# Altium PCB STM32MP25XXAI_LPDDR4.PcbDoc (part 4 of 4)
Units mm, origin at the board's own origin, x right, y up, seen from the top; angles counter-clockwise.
Board outline 172 x 137 mm, 4 copper layers (Top Layer, Signal Layer 1, Signal Layer 2, Bottom Layer), stack 1.614 mm thick; 188 components, 144 nets, 1216 pads, 838 vias.
Unrouted connection lines stored in the file: 13.
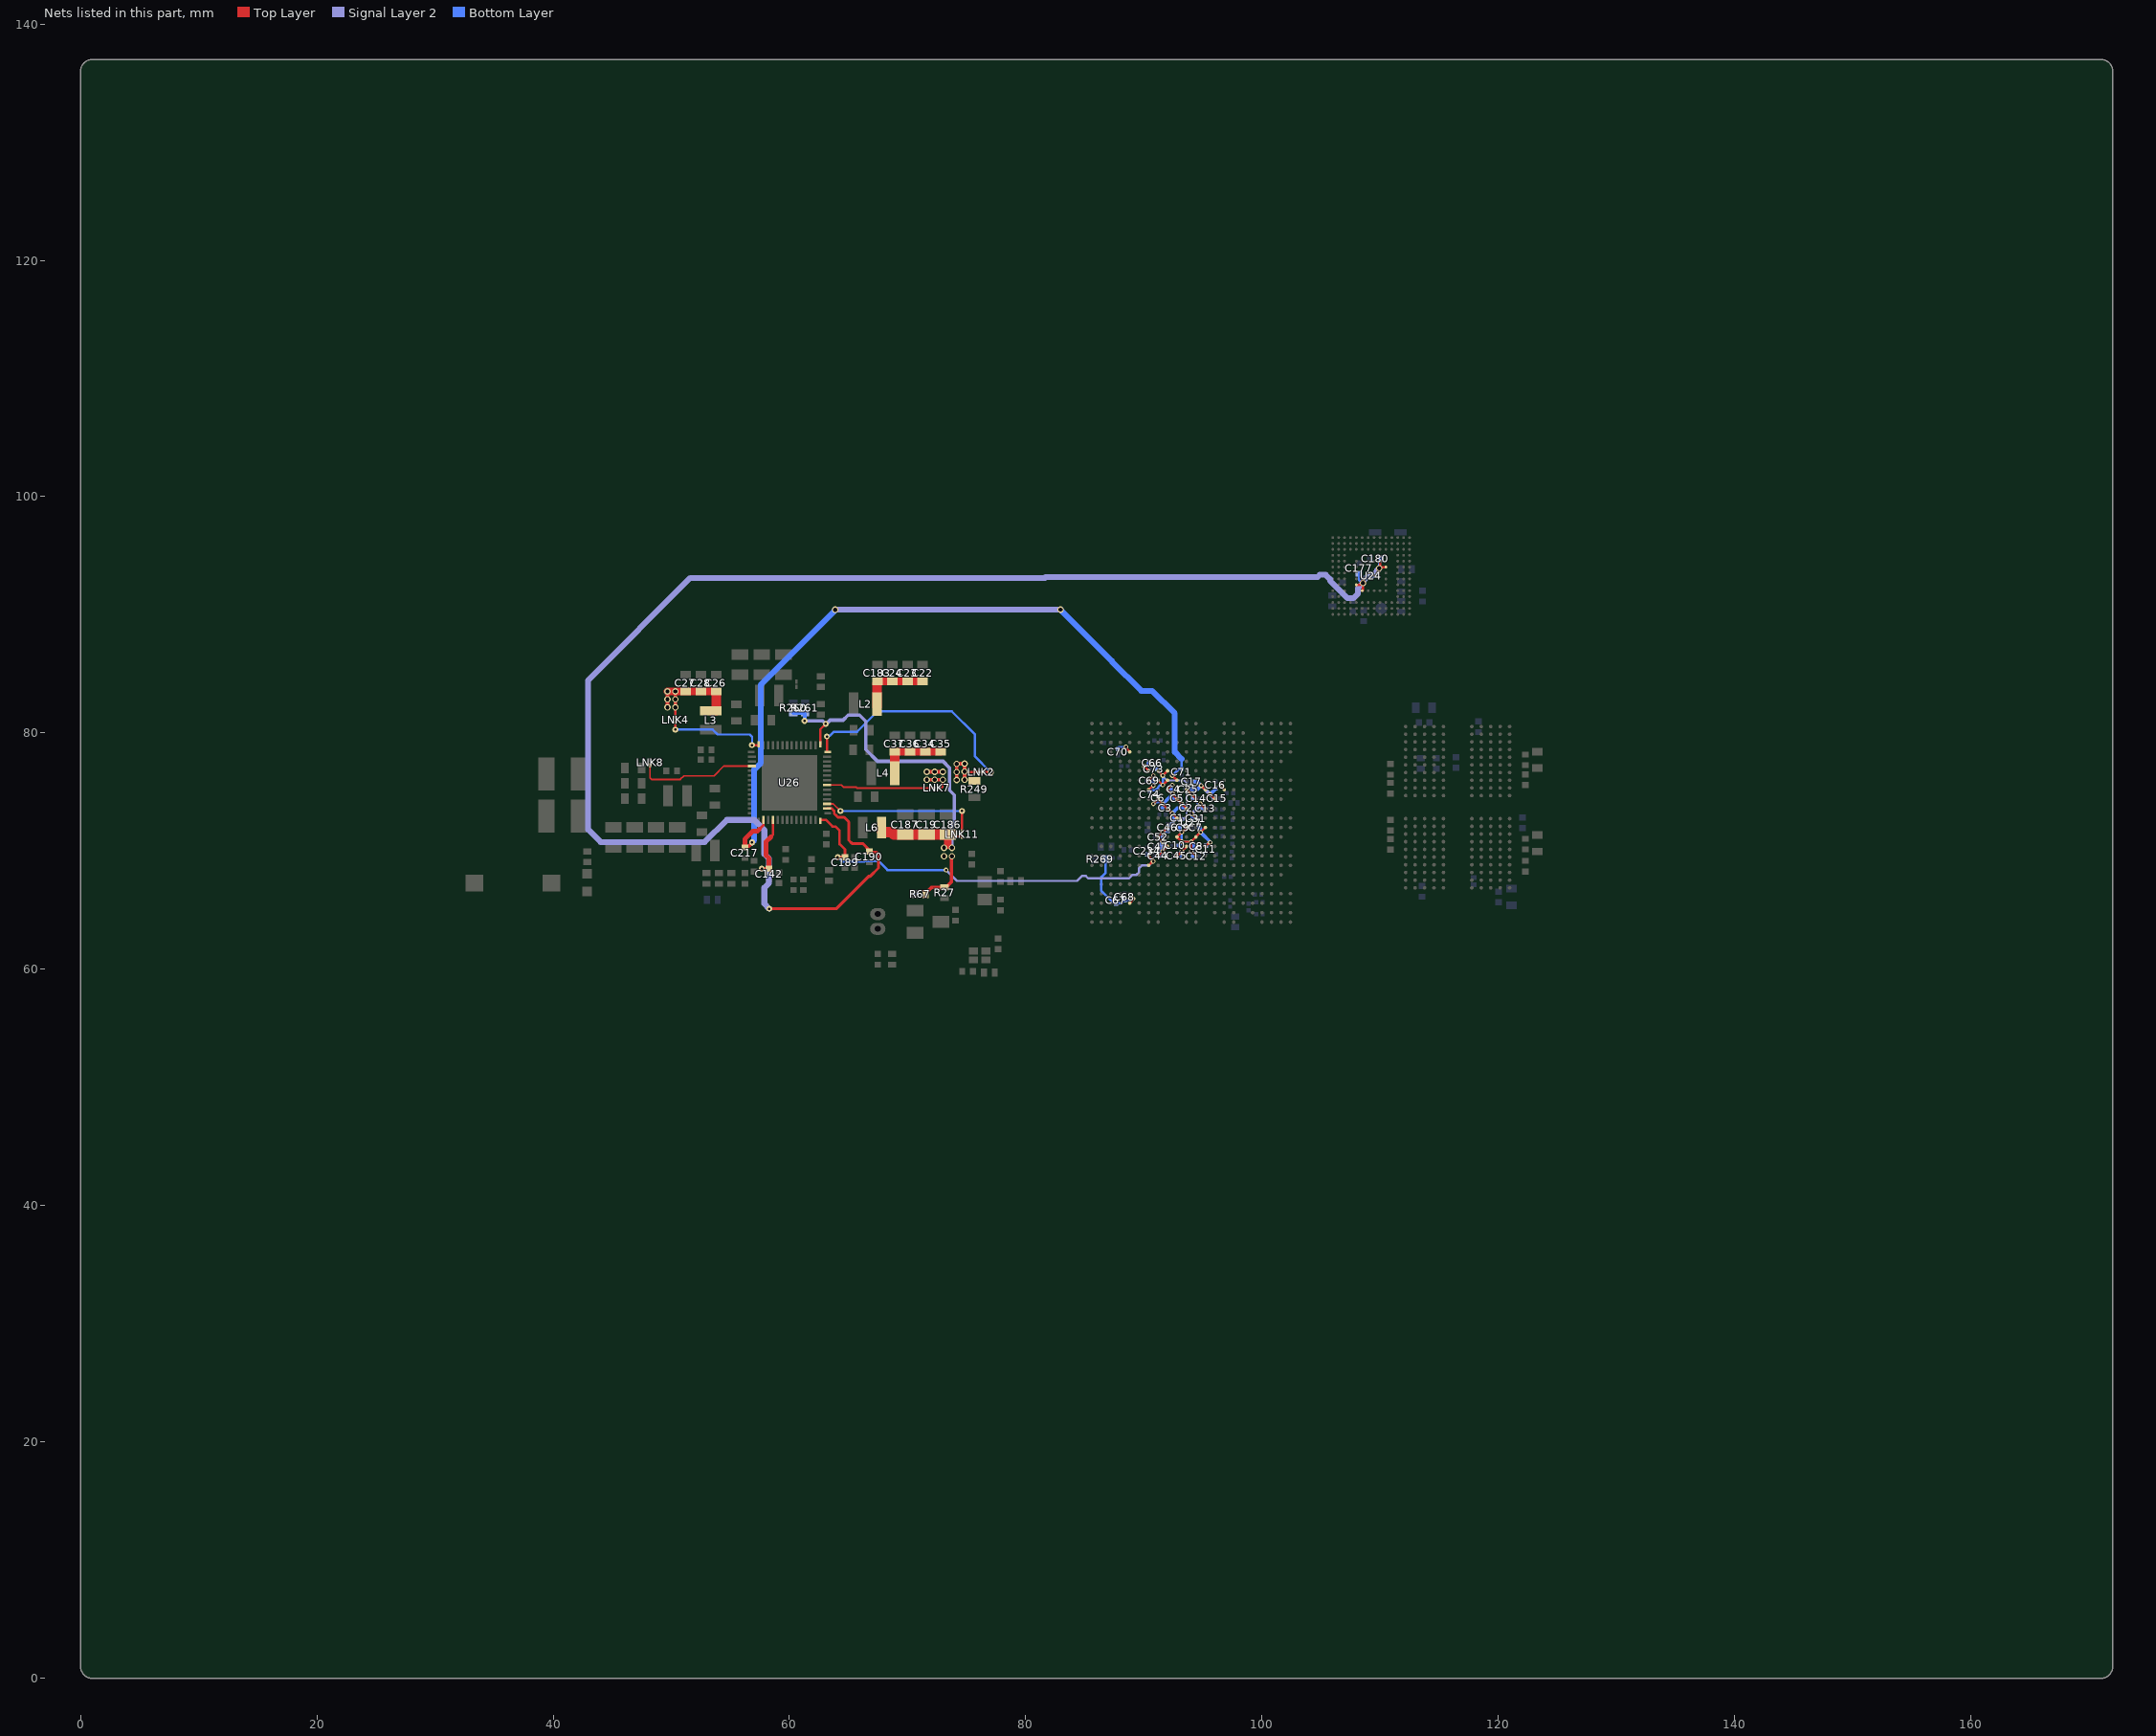
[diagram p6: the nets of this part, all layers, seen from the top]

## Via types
v1: diameter 0.55, hole 0.35, Top Layer to Bottom Layer, 387 vias
v2: diameter 0.4, hole 0.2, Top Layer to Bottom Layer, tented both sides, 173 vias
v3: diameter 0.5, hole 0.2, Top Layer to Bottom Layer, 146 vias
v4: diameter 0.4, hole 0.2, Top Layer to Bottom Layer, 129 vias
v5: diameter 0.5, hole 0.25, Top Layer to Bottom Layer, 3 vias

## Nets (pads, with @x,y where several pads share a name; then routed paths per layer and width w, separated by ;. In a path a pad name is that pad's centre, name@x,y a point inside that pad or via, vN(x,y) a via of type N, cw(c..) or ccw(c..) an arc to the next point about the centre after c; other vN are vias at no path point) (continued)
VDD_DDR_FB: LNK8.1 U26.46 | length 10.2
  Top Layer w0.15: LNK8.1@48.2,77.273 48.2,76.19 48.317,76.073 50.767,76.073 51.067,76.373 51.737,76.373 51.739,76.375 53.627,76.375 54.452,77.2 U26.46@56.83,77.2
VDD_EMMC: C177.2 C180.2 C190.1 U24.E6 U24.F5 U24.J10 U24.K9 U26.16 | length 132.1
  Top Layer w0.2: U24.E6@107.98,92.542 108.285,92.542 108.435,92.692 v1(108.53,92.692) 108.53,92.1 108.48,92.05 U24.F5@108.48,92.042 ; v1(109.905,93.942) v1@109.98,94.017 ; U24.J10@109.98,94.542 109.98,94.112 109.972,94.104 109.972,94.025 v1@109.98,94.017 ; U24.K9@110.48,94.042 110.1,94.042 110.067,94.009 109.988,94.009 v1@109.98,94.017
  Top Layer w0.21: U26.16@63.17,73.6 63.6,73.6 63.788,73.412 63.788,73.188 63.934,73.041
  Top Layer w0.25: v3(58.3,65.125) 63.96,65.125 66.7,67.865 66.822,67.865 67.535,68.578 67.535,69.764 67.389,69.91 66.805,69.91 C190.1@66.75,69.965 ; 63.932,73.038 64.098,72.872 64.628,72.872 65.025,72.475 65.025,70.925 65.3,70.65 66.195,70.65 C190.1@66.75,70.095
  Top Layer w0.5: v1(108.53,92.692) v1@108.53,92.706 ; v1@109.895,93.919 v1@109.895,93.932
  Signal Layer 2 w0.5: v3(58.3,65.125) 57.872,65.553 57.872,66.908 58.265,67.301 58.265,69.369 57.872,69.762 57.872,71.786 57.009,72.649 54.703,72.649 52.827,70.773 44.024,70.773 42.958,71.839 42.958,84.457 51.616,93.115 81.606,93.115 81.691,93.2 104.684,93.2 104.871,93.387 105.389,93.387 105.755,93.021 105.755,92.873 107.221,91.407 107.739,91.407 108.105,91.773 108.105,92.254 108.53,92.679 v1(108.53,92.692) ; v1@108.605,92.946 108.986,93.327 109.374,93.327 109.755,93.708 109.755,93.779 v1@109.895,93.919
  Bottom Layer w0.2: C177.2@108.19,93.455 108.19,92.949 108.459,92.68 v1@108.55,92.68 ; v1@109.925,93.93 109.925,94.614 C180.2@110.05,94.739
VDD_SDCARD: C142.1 U26.4 | length 5.1
  Top Layer w0.21: 58.425,71.2 58.6,71.375 U26.4@58.6,72.63
  Top Layer w0.3: v3(57.665,68.51) C142.1@58.275,68.51
  Top Layer w0.4: C142.1@58.275,68.51 58.275,69.393 58.01,69.658 58.01,70.785 58.425,71.2
VDDA1V8_AON: C189.2 C234.2 U26.14 U27.R7 U27.T7 | length 35.8
  Top Layer w0.2: U27.T7@90.4,68.8 90.687,69.087 90.757,69.087 v2(90.795,69.125) 90.795,69.178 90.4,69.573 U27.R7@90.4,69.6
  Top Layer w0.21: U26.14@62.6,72.63 63.11,72.63 63.648,72.092 63.887,72.092 64.245,71.734 64.245,70.602 64.7,70.147 C189.2@64.7,69.49
  Top Layer w0.3: v3(64.09,69.49) C189.2@64.7,69.49
  Signal Layer 2 w0.2: v2(73.253,68.406) 73.259,68.406 74.183,67.482 84.342,67.482 84.76,67.9 85.091,67.9 85.292,67.699 88.734,67.699 89.034,68 89.2,68 89.366,68 89.6,68.234 89.6,68.566 89.835,68.8 90.47,68.8 v2(90.795,69.125) v2@90.726,69.125
  Bottom Layer w0.2: v3(64.09,69.49) 64.48,69.1 66.321,69.1 66.392,69.171 67.535,69.171 68.3,68.406 v2(73.253,68.406) ; C234.2@90.275,69.735 90.441,69.569 90.441,69.443 90.76,69.125 v2(90.795,69.125)
VDDCORE: C1.1 C2.2 C3.2 C4.1 C5.2 C6.2 C22.2 C23.2 C24.2 C66.2 C69.2 C70.2 C183.2 L2.2 LNK2.2 R249.1 U27.D5 U27.F7 U27.G7 U27.H7 U27.H9 U27.J8 U27.J10 U27.K9 U27.K11 U27.L10 | length 26.2
  Top Layer w0.2: C22.2@71.275,84.375 C22.2@71.323,84.423 ; v1@74.87,76.685 LNK2.2@75.98,76.685 ; v2(88.475,78.825) 88.475,78.725 U27.D5@88.8,78.4 ; v2(90,77.2) U27.F7@90.4,76.8 U27.F7@90.425,76.8 ; U27.H7@90.4,75.2 90.425,75.2 90.775,75.55 v2(90.8,75.55) ; U27.G7@90.4,76 v2(90.8,76.4) ; v2(90.8,74) U27.J8@91.2,74.4 v2(91.6,74) v2(92.4,73.2) U27.L10@92.8,72.8 ; v2(92.4,75.6) U27.H9@92,75.2 v2@92.425,74.775 ; v2(92.425,74.85) v2@92.425,74.775 ; U27.K11@93.6,73.6 v2(93.2,74) U27.J10@92.8,74.4 v2@92.425,74.775
  Top Layer w0.3: v1@74.151,77.404 v1(74.826,77.404) v1(74.826,76.729) ; v1(74.156,76.024) v1(74.156,76.699) v1(74.156,77.374) ; v1(74.826,76.054) v1(74.826,76.729) ; v1@74.87,76.685 v1(74.826,76.729)
  Top Layer w0.64: C183.2@67.45,84.375 C24.2@68.725,84.375 C23.2@70,84.375 C22.2@71.275,84.375
  Top Layer w0.8: L2.2@67.415,82.2 L2.2@67.415,82.45 C183.2@67.415,84.173
  Bottom Layer w0.2: C70.2@87.8,78.7 87.9,78.8 88.038,78.8 v2@88.4,78.8 ; v2(90,77.2) 90.038,77.238 90.188,77.238 C66.2@90.425,77.475 ; v2(90.8,75.55) 90.777,75.572 90.777,75.948 C69.2@90.755,75.97 90.777,75.992 90.777,76.378 v2(90.8,76.4)
  Bottom Layer w0.3: v2(90.8,74) 91,74.2 91.4,74.2 v2(91.6,74) ; C3.2@91.55,73.65 91.55,73.95 v2(91.6,74) ; v2(92.4,75.6) 92.275,75.475 C4.1@92.275,75.25 92.275,75 v2(92.425,74.85) ; C1.1@92.55,72.825 92.55,73.05 v2(92.4,73.2) 92.85,73.65 C2.2@93.326,73.65 93.325,73.875 v2(93.2,74) ; C5.2@92.551,74.475 92.55,74.725 v2(92.425,74.85) ; v2(91.6,74) 92.425,74.825 v2(92.425,74.85)
VDDCORE_FB: LNK2.1 U26.28 | length 19.9
  Top Layer w0.2: U26.28@63.17,78.4 v3(63.17,79.7) ; LNK2.1@76.444,76.687 v1@77.031,76.685
  Bottom Layer w0.2: v3(63.17,79.7) 63.227,79.757 63.401,79.757 63.754,80.111 65.734,80.111 67.457,81.833 73.744,81.833 75.675,79.902 75.675,78.041 v1(77.033,76.683)
VDDCPU: C13.1 C14.2 C15.2 C16.1 C17.2 C25.2 C26.2 C27.2 C28.2 C31.2 L3.2 LNK4.1 U27.H11 U27.H13 U27.H15 U27.J12 U27.J14 U27.K13 U27.L12 | length 21.1
  Top Layer w0.2: LNK4.1@50.35,81.35 v1(50.35,82.173) ; U27.H11@93.6,75.2 93.627,75.2 93.924,74.903 94.052,74.903 94.128,74.827 94.128,74.699 94.4,74.427 U27.J12@94.4,74.4 ; v2(94.045,73.155) U27.L12@94.4,72.8 ; v2(94.775,74.005) 95.18,73.6 U27.K13@95.2,73.6 ; v2(94.845,75.555) U27.H13@95.2,75.2 ; v2(95.595,74.805) U27.J14@96,74.4 ; v2(96.54,75.591) 96.578,75.553 96.578,75.449 96.8,75.227 U27.H15@96.8,75.2
  Top Layer w0.3: v1(49.675,82.173) v1(49.675,82.848) v1(49.675,83.523) v1(50.35,83.523) v1(50.35,82.848) v1(50.35,82.173)
  Top Layer w0.64: v1(49.675,83.523) 49.675,83.525 C27.2@51.2,83.525 C28.2@52.5,83.525 C26.2@53.8,83.525
  Top Layer w0.8: L3.2@53.35,81.875 53.8,81.875 53.8,83.173
  Signal Layer 2 w0.3: v2(94.045,73.155) 94.756,73.866 94.756,73.986 v2(94.775,74.005) ; v2(94.845,75.555) v2(95.595,74.805)
  Bottom Layer w0.1: C14.2@94.15,74.48 94.15,74.379 94.524,74.005 v2(94.775,74.005)
  Bottom Layer w0.2: v2(94.045,73.155) 94.045,72.855 C31.2@94.125,72.775 ; v2@94.775,73.978 v2(94.775,74.005) ; C13.1@94.95,73.625 94.95,73.803 ; v2(95.595,74.805) 95.633,74.767 95.633,74.692 C15.2@95.875,74.45
  Bottom Layer w0.3: v2(94.095,74.865) 94.095,74.892 94.05,74.937 94.05,75.225 C25.2@94.025,75.25 94.548,75.25 v2@94.853,75.555 ; C17.2@94.325,75.875 94.525,75.875 v2(94.845,75.555) ; v2@94.775,73.978 94.95,73.803 ; v2(95.595,74.805) C16.1@96.095,75.305
VDDCPU_FB: LNK4.2 U26.42 | length 8.6
  Top Layer w0.2: v3(50.35,80.29) LNK4.2@50.35,80.9 ; v3(56.825,78.975) U26.42@57.395,78.975
  Bottom Layer w0.2: v3@50.37,80.287 53.499,80.287 53.914,79.872 56.643,79.872 56.845,79.67 v3@56.845,78.972
VDDGPU: C7.2 C8.2 C9.2 C10.2 C11.1 C12.2 C34.2 C35.2 C36.2 C37.2 L4.2 LNK7.2 U27.M11 U27.M13 U27.N10 U27.N12 U27.P13 U27.R12 | length 21.3
  Top Layer w0.15: LNK7.2@72.675,75.35 72.682,75.358 72.885,75.358 72.973,75.445 v1(72.973,76.038)
  Top Layer w0.2: C35.2@73.05,78.393 C35.2@73.098,78.345 ; U27.M11@93.6,72 v2(93.2,71.6) U27.N10@92.8,71.2 93.197,70.803 93.997,70.803 v2(94,70.8) ; U27.R12@94.4,69.6 v2(94,70) v2(94,70.8) ; U27.P13@95.2,70.4 95.487,70.687 95.562,70.687 v2(95.6,70.725) ; U27.M13@95.2,72 v2(94.8,71.6) v2(94,70.8)
  Top Layer w0.3: v1(71.623,76.038) v1(72.298,76.038) v1(72.973,76.038) ; v1(71.623,76.713) v1(72.298,76.713) v1(72.973,76.713)
  Top Layer w0.64: C37.2@68.9,78.4 C36.2@70.2,78.4 C34.2@71.5,78.4 C35.2@72.8,78.4
  Top Layer w0.8: L4.2@68.925,76.6 68.925,78.073
  Bottom Layer w0.2: C9.2@93.025,72 93.025,71.775 v2(93.2,71.6) 93.197,71.598 93.197,70.808 93.195,70.805 93.197,70.803 93.997,70.803 v2(94,70.8) ; v2(95.6,70.725) v2@95.61,70.715
  Bottom Layer w0.3: C10.2@92.95,70.48 93.176,70.706 93.176,70.786 v2@93.195,70.805 ; v2(94,70.8) 94.175,70.625 94.175,70.175 v2(94,70) 94.2,69.8 C12.2@94.2,69.575 ; C7.2@94.675,72 94.8,71.875 v2(94.8,71.6) 94.833,71.567 95.581,70.819 95.581,70.744 v2(95.6,70.725) 95.581,70.706 95.506,70.706 C11.1@95.25,70.45
  other v2: 93.2,70.805
VDDGPU_FB: LNK7.1 U26.21 | length 9.3
  Top Layer w0.15: U26.21@63.05,75.6 64.383,75.6 64.56,75.423 65.64,75.423 65.713,75.35 LNK7.1@72.225,75.35
VDDIO: C19.2 C44.1 C45.2 C46.2 C47.1 C52.2 C73.2 C74.2 C186.2 C187.2 L6.2 LNK11.2 R27.2 R67.2 R260.2 R261.2 U26.29 U27.F8 U27.F9 U27.G8 U27.G9 U27.M9 U27.N8 U27.P9 U27.P11 U27.R8 U27.R10 | length 61.4
  Top Layer w0.2: U26.29@62.6,79.045 62.6,80.298 v3(63.075,80.773) ; C186.2@73.4,71.4 73.585,71.215 LNK11.2@74.6,71.215 ; U27.R8@91.2,69.6 v2(91.575,69.975) U27.P9@92,70.4 v2(91.6,70.8) U27.N8@91.2,71.2 v2(91.6,71.6) U27.M9@92,72 ; U27.G8@91.2,76 91.599,75.6 U27.G9@92,76 ; U27.F8@91.2,76.8 v2(91.6,76.4) U27.F9@92,76.8 ; U27.R10@92.8,69.6 v2(93.2,70) U27.P11@93.6,70.4
  Top Layer w0.3: R67.2@71.525,66.375 71.525,66.44 72.01,66.925 R27.2@73.125,66.925 73.23,67.03 73.339,67.03 73.712,67.402 73.712,69.52 v1(73.752,69.56) ; v1(73.077,69.56) v1@73.125,69.512
  Top Layer w0.64: 73.4,70.525 C186.2@73.4,70.955
  Top Layer w0.9: L6.2@67.85,71.6 68.65,71.6 68.85,71.4 C187.2@69.8,71.4 C19.2@71.6,71.4 C186.2@73.4,71.4
  Signal Layer 2 w0.15: v2(91.599,75.599) 91.971,75.971 91.962,75.98 ; v2@91.6,76.338 v2@91.6,76.342 ; v2(91.6,76.4) v2@91.6,76.342 ; 93.301,72.703 93.608,73.01 93.608,75.783 93.411,75.98 91.962,75.98 ; v2@91.6,76.342 91.962,75.98
  Signal Layer 2 w0.3: v3(61.284,81.027) 62.799,81.027 63.05,80.776 v3@63.075,80.776 ; v3(63.075,80.773) 63.129,80.773 63.44,81.084 64.543,81.084 64.973,81.513 65.931,81.513 66.455,80.989 66.455,78.601 67.456,77.6 72.999,77.6 73.551,77.048 73.551,75.156 73.951,74.756 73.951,72.573 73.752,72.375 v1(73.752,70.285) ; v2(91.575,69.975) 91.6,70 v2(91.6,71.6) 92.703,72.703 93.301,72.703
  Bottom Layer w0.2: C74.2@90.5,75.05 90.575,75.125 90.667,75.125 90.692,75.15 90.931,75.15 90.946,75.165 90.981,75.165 91.2,75.384 91.2,75.419 91.342,75.561 91.561,75.561 v2(91.599,75.599) 91.6,76.4 91.6,76.45 C73.2@91.125,76.925
  Bottom Layer w0.3: R260.2@60.33,81.68 R261.2@61.305,81.68 61.294,81.669 61.294,81.038 v3(61.284,81.027) ; C44.1@91.475,69.6 91.475,69.875 v2(91.575,69.975) 91.475,70.075 91.475,70.675 v2(91.6,70.8) 91.475,70.925 91.475,71.475 91.725,71.725 C46.2@92.025,71.725 ; C45.2@93.075,69.6 93.075,69.875 v2(93.2,70) v2@93.225,70
  other v1: 73.077,70.285
VDDIO_FB: LNK11.1 U26.17 | length 13.4
  Top Layer w0.15: U26.17@63.17,74 63.7,74 64.303,73.397 v3(64.315,73.397)
  Top Layer w0.2: LNK11.1@74.6,71.665 v3(74.6,73.4)
  Bottom Layer w0.15: v3(64.315,73.397) v3@74.597,73.397
VDDIO_SDCARD: C71.2 C217.1 U26.2 U27.G10 | length 65.5
  Top Layer w0.2: v2(92.4,76.4) U27.G10@92.8,76
  Top Layer w0.21: 57.459,71.873 57.8,72.214 U26.2@57.8,72.63
  Top Layer w0.3: C217.1@56.225,70.38 56.27,70.425 56.559,70.425 56.835,70.701 v3(56.835,70.737)
  Top Layer w0.4: C217.1@56.225,70.32 56.225,70.38 56.225,71.015 56.899,71.69 57.275,71.69 57.459,71.873
  Signal Layer 2 w0.5: v1(63.865,90.43) 63.867,90.432 82.942,90.432 v1(82.945,90.435)
  Bottom Layer w0.2: v2(92.4,76.4) 92.95,76.95 C71.2@93.201,76.95 93.201,77.799
  Bottom Layer w0.5: v3(56.835,70.737) 57.009,70.911 57.009,76.91 57.581,77.482 57.581,81.596 57.575,81.601 57.575,82.099 57.581,82.104 57.581,84.092 63.855,90.367 63.855,90.42 v1(63.865,90.43) ; v1@82.945,90.444 v1(82.945,90.435) 87.294,86.086 87.294,86.055 89.779,83.57 90.696,83.57 92.605,81.661 92.605,78.395 93.2,77.8
VREF+: C67.2 C68.2 R269.2 U27.Y5 | length 6.6
  Top Layer w0.2: U27.Y5@88.8,65.6 89.037,65.837 89.037,65.942 v2(89.076,65.981)
  Bottom Layer w0.2: R269.2@86.754,69.315 86.754,68.159 86.402,67.808 86.402,66.63 87.387,65.645 87.585,65.645 87.63,65.6 88.125,65.6 C68.2@88.375,65.85 88.904,65.85 89.035,65.981 v2(89.076,65.981)
pads on no net: U2.A1 U2.A2 U2.A8 U2.A11 U2.A12 U2.AA1 U2.AA12 U2.AB1 U2.AB2 U2.AB11 U2.AB12 U2.B1 U2.B12 U2.G11 U2.H3 U2.J5 U2.K5 U2.K8 U2.N5 U2.N8 U2.P5 U2.R3 U24.A1 U24.A2 U24.A7 U24.A8 U24.A9 U24.A10 U24.A11 U24.A12 U24.A13 U24.A14 U24.B1 U24.B7 U24.B8 U24.B9 U24.B10 U24.B11 U24.B12 U24.B13 U24.B14 U24.C1 U24.C3 U24.C5 U24.C7 U24.C8 U24.C9 U24.C10 U24.C11 U24.C12 U24.C13 U24.C14 U24.D1 U24.D2 U24.D3 U24.D4 U24.D12 U24.D13 U24.D14 U24.E1 U24.E2 U24.E3 U24.E5 U24.E8 U24.E9 U24.E10 U24.E12 U24.E13 U24.E14 U24.F1 U24.F2 U24.F3 U24.F10 U24.F12 U24.F13 U24.F14 U24.G1 U24.G2 U24.G3 U24.G10 U24.G12 U24.G13 U24.G14 U24.H1 U24.H2 U24.H3 U24.H12 U24.H13 U24.H14 U24.J1 U24.J2 U24.J3 U24.J12 U24.J13 U24.J14 U24.K1 U24.K2 U24.K3 U24.K6 U24.K7 U24.K10 U24.K12 U24.K13 U24.K14 U24.L1 U24.L2 U24.L3 U24.L12 U24.L13 U24.L14 U24.M1 U24.M2 U24.M3 U24.M7 U24.M8 U24.M9 U24.M10 U24.M11 U24.M12 U24.M13 U24.M14 U24.N1 U24.N3 U24.N6 U24.N7 U24.N8 U24.N9 U24.N10 U24.N11 U24.N12 U24.N13 U24.N14 U24.P1 U24.P2 U24.P7 U24.P8 U24.P9 U24.P10 U24.P11 U24.P12 U24.P13 U24.P14 U27.A2 U27.A3 U27.A4 U27.A7 U27.A8 U27.A11 U27.A12 U27.A15 U27.A16 U27.A21 U27.AA1 U27.AA2 U27.AA3 U27.AA4 U27.AA6 U27.AA7 U27.AA8 U27.AA10 U27.AA11 U27.AA12 U27.AA14 U27.AA15 U27.AA16 U27.AA18 U27.AA19 U27.AA20 U27.AA21 U27.AB2 U27.AB3 U27.AB4 U27.AB7 U27.AB8 U27.AB11 U27.AB12 U27.AB15 U27.AB16 U27.AB19 U27.AB20 U27.AB21 U27.B1 U27.B2 U27.B3 U27.B4 U27.B5 U27.B7 U27.B8 U27.B9 U27.B11 U27.B12 U27.B13 U27.B15 U27.B16 U27.B17 U27.B20 U27.B21 U27.C1 U27.C2 U27.C3 U27.C5 U27.C6 U27.C8 U27.C9 U27.C10 U27.C11 U27.C12 U27.C13 U27.C14 U27.C15 U27.C16 U27.C17 U27.C20 U27.D1 U27.D2 U27.D3 U27.D4 U27.D6 U27.D7 U27.D8 U27.D9 U27.D10 U27.D11 U27.D12 U27.D13 U27.D14 U27.D15 U27.D16 U27.D19 U27.E3 U27.E4 U27.E6 U27.E7 U27.E8 U27.E9 U27.E10 U27.E11 U27.E12 U27.E13 U27.E14 U27.E15 U27.E18 U27.F2 U27.F3 U27.F4 U27.F5 U27.F11 U27.F12 U27.F13 U27.F14 U27.F15 U27.G1 U27.G2 U27.G3 U27.G4 U27.G5 U27.G11 U27.G12 U27.G13 U27.G14 U27.G16 U27.H1 U27.H2 U27.H3 U27.H4 U27.H5 U27.H6 U27.J3 U27.J4 U27.J5 U27.J6 U27.J7 U27.K2 U27.K3 U27.K4 U27.K5 U27.K6 U27.K7 U27.K17 U27.K18 U27.L1 U27.L2 U27.L3 U27.L4 U27.L5 U27.L6 U27.L7 U27.L20 U27.M1 U27.M2 U27.M3 U27.M4 U27.M5 U27.M6 U27.M18 U27.N3 U27.N4 U27.N5 U27.N6 U27.P2 U27.P3 U27.P4 U27.P5 U27.P16 U27.P17 U27.R3 U27.R4 U27.R5 U27.R6 U27.R17 U27.R18 U27.R19 U27.T1 U27.T2 U27.T8 U27.T9 U27.T10 U27.T11 U27.T12 U27.T13 U27.T14 U27.T15 U27.T17 U27.T19 U27.U4 U27.U5 U27.U8 U27.U9 U27.U10 U27.U11 U27.U12 U27.U13 U27.U14 U27.U15 U27.U16 U27.U18 U27.U19 U27.V4 U27.V5 U27.V6 U27.V8 U27.V9 U27.V10 U27.V11 U27.V12 U27.V13 U27.V14 U27.V15 U27.V16 U27.V17 U27.W1 U27.W2 U27.W3 U27.W4 U27.W6 U27.W7 U27.W9 U27.W10 U27.W11 U27.W12 U27.W13 U27.W14 U27.W15 U27.W17 U27.Y1 U27.Y3 U27.Y4 U27.Y6 U27.Y7 U27.Y8 U27.Y9 U27.Y10 U27.Y11 U27.Y12 U27.Y13 U27.Y14 U27.Y15 U27.Y17 U27.Y18 U27.Y20
copper on no net: | length 328.5
  Top Layer w0.09: 81.172,76.702 85.898,76.702 86.105,76.495 88.305,76.495 88.8,76 ; 81.614,76.882 86.261,76.882 86.343,76.8 86.4,76.8 ; 81.76,77.09 86.513,77.09 86.803,76.8 87.2,76.8 ; 82.23,77.27 86.59,77.27 86.775,77.085 87.332,77.085 87.342,77.075 87.575,76.842 87.59,76.827 87.973,76.827 88,76.8 ; 82.334,77.52 86.693,77.52 86.898,77.315 87.427,77.315 87.437,77.305 87.657,77.085 88.515,77.085 88.8,76.8 ; 82.986,77.7 87.043,77.7 87.143,77.6 87.2,77.6 ; 83.083,77.935 87.665,77.935 88,77.6 ; 83.395,70.522 83.453,70.522 83.53,70.445 85.911,70.445 86.233,70.123 86.549,70.123 86.777,69.895 87.556,69.895 87.76,70.099 ; 83.448,70.265 85.754,70.265 86.124,69.895 86.522,69.895 86.817,69.6 87.2,69.6 ; 83.537,70.707 83.619,70.625 86.175,70.625 86.4,70.4 ; 83.604,70.895 83.694,70.805 86.412,70.805 86.695,70.522 86.695,70.28 86.9,70.075 87.406,70.075 87.731,70.4 88,70.4 ; 83.673,71.08 83.758,70.995 86.477,70.995 87.032,70.44 87.16,70.44 87.2,70.4 ; 83.685,78.115 85.718,78.115 86.003,78.4 86.4,78.4 ; 83.748,71.26 83.833,71.175 86.551,71.175 87.031,70.695 88.295,70.695 88.8,71.2 ; 83.789,78.365 85.565,78.365 85.6,78.4 ; 83.877,71.64 83.982,71.535 86.75,71.535 87.045,71.24 87.16,71.24 87.2,71.2 ; 84.075,71.875 84.235,71.715 86.827,71.715 87.047,71.495 88.295,71.495 88.8,72 ; 84.174,72.075 84.249,72 ; 84.615,68.995 85.224,68.995 85.354,69.125 87.525,69.125 88,69.6 ; 84.65,68.41 85.613,68.41 86.003,68.8 86.4,68.8 ; 84.862,74.565 86.439,74.565 86.939,75.065 87.011,75.065 87.146,75.2 87.2,75.2 ; 85.472,78.675 85.482,78.685 86.603,78.685 86.875,78.413 86.875,78.3 87.06,78.115 87.715,78.115 88,78.4 ; 85.472,78.925 85.482,78.915 86.642,78.915 87.157,78.4 87.2,78.4 ; 86.115,75.475 86.125,75.475 86.4,75.2 ; 86.865,75.665 87.2,76 ; 87.359,70.885 87.361,70.885 87.683,70.885 87.998,71.2 ; 87.424,60.877 89.925,63.377 89.925,64.197 90.105,64.377 90.105,65.305 90.4,65.6 ; 87.634,82.95 89.145,81.439 89.145,80.673 89.52,80.298 89.52,79.693 89.885,79.328 89.885,78.115 90.4,77.6 ; 87.634,60.832 90.105,63.303 90.105,64.122 90.4,64.417 90.4,64.8 ; 87.738,83.2 89.395,81.543 89.395,81.439 89.395,80.91 89.394,80.909 89.394,80.776 89.75,80.42 89.75,79.788 90.115,79.424 90.115,78.273 90.273,78.115 90.347,78.115 90.4,78.168 90.4,78.4 ; 87.796,81.5 88.106,81.19 88.285,81.011 88.285,79.715 88.8,79.2 ; 87.826,82.15 88.715,81.261 88.715,80.495 89.085,80.125 89.085,78.915 89.6,78.4 ; 87.87,60.813 90.4,63.343 90.4,64 ; 87.9,81.75 88.535,81.115 88.535,81.011 88.535,79.853 88.673,79.715 88.747,79.715 88.8,79.768 88.8,80 ; 87.93,82.4 88.965,81.365 88.965,80.599 89.335,80.229 89.335,79.053 89.473,78.915 89.547,78.915 89.6,78.968 89.6,79.2 ; 88.124,70.099 88.405,70.38 88.78,70.38 88.8,70.4 ; 89.745,63.452 89.745,64.271 89.925,64.451 89.925,65.925 90.4,66.4 ; v2@90.8,78 91.2,77.6 ; v2(90.846,66.845) 91.2,67.2 ; v2(90.846,67.645) 91.2,68 ; v2@90.865,65.226 v2(90.846,65.245) 91.2,65.6 ; v2(91.525,66.825) 91.575,66.825 91.95,67.2 92,67.2 ; 92.145,63.204 92.145,65.071 92.505,65.431 92.505,65.722 92.505,66.905 92.8,67.2 ; 92.325,62.976 92.325,64.997 92.603,65.275 92.744,65.275 92.8,65.331 92.8,65.6 ; 92.505,62.82 92.505,64.922 92.678,65.095 92.969,65.095 93.12,65.247 93.12,66.08 92.8,66.4 ; 92.765,62.66 92.765,64.346 92.825,64.406 92.825,64.775 92.8,64.8 ; v2(93.05,66.775) 93.294,67.019 93.364,67.019 93.545,67.2 93.6,67.2 ; 93.29,82.424 93.29,80.31 93.6,80 ; 93.6,76 v2@94,76.4 ; v2(93.898,66.003) 93.93,66.035 93.93,66.75 94.38,67.2 94.4,67.2 ; 93.925,62.425 93.925,65.173 94.105,65.353 94.105,65.722 94.25,65.868 94.25,66.239 94.4,66.389 94.4,66.4 ; v2(93.95,67.6) 94.35,68 94.4,68 ; 94.105,62.105 94.105,64.122 94.4,64.417 94.4,64.8 ; 94.4,61.975 94.4,64 ; 94.4,65.6 94.695,65.305 94.695,61.851 ; 95.045,81.28 95.045,80.533 94.915,80.403 94.915,79.882 95.2,79.597 95.2,79.2 ; 95.2,67.2 95.541,67.541 95.541,67.734 v2(95.6,67.793) ; 95.275,61.5 95.275,65 95.495,65.22 95.495,66.775 95.495,67.2 95.858,67.563 96.163,67.563 96.4,67.8 96.4,68.048 96,68.448 96,68.8 ; 95.455,61.383 95.455,64.913 95.675,65.133 95.675,66.875 96,67.2 ; 95.585,81.665 95.585,80.308 95.69,80.203 95.69,78.71 96,78.4 ; 95.635,61.266 95.635,64.838 96,65.203 96,65.6 ; 95.765,81.835 95.765,80.383 95.87,80.278 95.87,79.361 96,79.231 96,79.2 ; 95.833,61.167 95.833,64.576 96,64.743 96,64.8 ; 95.945,81.98 95.945,80.457 96.05,80.352 96.05,79.588 96.31,79.328 96.31,77.91 96,77.6 ; 96,66.4 96.295,66.105 96.295,64.62 96.081,64.406 96.081,61.118 ; 96,68 96,68.025 ; 96.125,82.2 96.125,80.532 96.23,80.427 96.23,79.663 96.49,79.403 96.49,78.8 96.49,78.71 96.8,78.4 ; 96.305,82.495 96.305,80.606 96.41,80.501 96.41,79.866 96.781,79.495 96.781,79.219 96.8,79.2 ; 96.315,60.815 96.315,64.385 96.475,64.545 96.475,66.875 96.8,67.2 ; 96.485,82.74 96.485,80.681 96.59,80.576 96.59,80.225 96.8,80.015 96.8,80 ; 99.2,64.8 99.166,64.834 98.961,64.834 98.875,64.749 98.875,63.825 99.3,63.4 99.3,61.425 99.525,61.2 ; 99.2,65.6 99.192,65.592 99.192,65.381 99.035,65.224 98.997,65.224 98.625,64.852 98.625,63.721 99.05,63.296 99.05,61.321 99.275,61.096 ; 100,64 99.96,64.04 99.96,64.219 99.904,64.275 99.756,64.275 99.7,64.219 99.7,63.8 99.775,63.725 100.025,63.475 100.025,61.9 100.548,61.378 100.799,61.126 ; 100,64.8 99.96,64.76 99.96,64.581 99.904,64.525 99.622,64.525 99.45,64.354 99.45,63.696 99.775,63.371 99.775,61.796 100.361,61.211 100.549,61.022 ; 100.525,62.771 100.525,63.446 100.285,63.687 100.285,64.106 100.76,64.581 100.76,64.76 ; 100.76,64.04 100.709,63.989 100.588,63.989 100.535,63.937 100.535,63.79 100.775,63.55 100.775,62.875 ; 101.6,64 101.56,64.04 101.56,64.195 101.504,64.251 101.425,64.251 101.335,64.16 101.335,63.85 101.445,63.74 101.445,63.509 102,62.954 102.85,62.104 103.082,61.872 ; 101.6,64.8 101.56,64.76 101.56,64.585 101.5,64.525 101.346,64.525 101.085,64.264 101.085,63.746 101.195,63.637 101.195,63.543 101.195,63.406 101.75,62.85 102.6,62 102.832,61.768
  Top Layer w0.1: 81.172,76.29 85.72,76.29 86.01,76 86.4,76 ; 83.388,70.325 83.448,70.265 ; 83.838,62.335 84.635,63.132 84.635,63.791 85.244,64.4 86,64.4 86.4,64.8 ; 84.249,72 85.6,72 ; 84.29,68.41 84.65,68.41 ; 84.378,68.994 84.614,68.994 84.615,68.995 ; 84.412,68.8 85.6,68.8 ; 85.063,65.025 85.063,65.473 85.48,65.89 85.89,65.89 86.4,66.4 ; 85.199,73.085 85.394,73.28 85.792,73.28 86.162,72.91 86.236,72.91 86.346,72.8 86.4,72.8 ; 85.38,75.659 85.401,75.68 86.126,75.68 86.141,75.665 86.865,75.665 ; 85.459,75.469 85.48,75.49 85.79,75.49 85.805,75.475 86.115,75.475 ; v2(87.6,73.2) 88,73.6 ; 87.76,70.099 88.124,70.099 ; 87.914,74.011 89.989,74.011 90.4,73.6 ; 88,67.2 88,66.81 88.49,66.32 88.49,63.265 ; v2(88.4,72.4) 88.8,72.8 ; v2(88.4,73.2) 88.8,73.6 ; v2(88.4,74.8) 88.8,74.4 ; v2(88.4,75.6) 88.8,75.2 ; 88.722,63.227 88.722,64.601 89.31,65.189 89.31,65.72 89.6,66.01 89.6,66.4 ; 88.912,63.149 88.912,64.522 89.6,65.21 89.6,65.6 ; 89.102,63.07 89.102,64.302 89.6,64.8 ; v2(89.2,71.6) 89.6,72 ; v2(89.2,72.4) 89.6,72.8 ; v2(89.2,73.2) 89.6,73.6 ; v2(89.2,74.8) 89.6,74.4 ; v2(89.2,75.6) 89.6,75.2 ; v2(89.2,78) 89.6,77.6 ; v2(90.8,68.4) 91.2,68.8 ; v2(91.6,67.6) 92,68 ; v2(91.6,68.4) 92,68.8 ; v2(92.4,67.6) 92.8,68 ; v2(92.4,68.4) 92.8,68.8 ; 92.8,78.4 v2@93.2,78.8 ; v2(93.2,67.6) 93.6,68 ; v2(93.2,68.4) 93.6,68.8 ; v2(94,68.4) 94.4,68.8 ; 94.4,76.8 v2@94.8,77.2 ; v2(94.8,76.4) 95.2,76 ; v2(95.6,68.4) 96,68 ; 97.536,63.661 97.603,63.728 97.603,63.997 97.6,64 ; 97.6,64.8 97.6,64.439 97.89,64.149 97.89,63.88 97.823,63.813 97.823,63.637 97.756,63.569 ; 97.6,67.2 v2(98,66.8) ; 98.35,61.975 98.08,62.245 98.08,64.88 98.48,65.28 98.48,65.466 98.4,65.546 98.4,65.6 ; 98.4,66.4 98.4,66.01 98.7,65.71 98.7,65.189 98.3,64.789 98.3,62.336 98.57,62.066 ; 98.4,67.2 98.643,66.957 98.643,66.857 v2(98.7,66.8)
  Top Layer w0.11: v2(94.65,66) 94.606,66 94.662,66.055 94.855,66.055 95.2,66.4 ; v2(94.8,66.8) 94.8,67.602 95.198,68 95.2,68 ; v2(94.8,69.075) 95.2,68.8 ; 96.8,80.8 96.8,82.85
  Top Layer w0.2: 88.8,67.2 88.827,67.2 89.103,66.924 89.226,66.924 v2(89.264,66.886) ; v2(90.01,73.23) 90.01,73.21 90.4,72.82 90.4,72.8
  Bottom Layer w0.11: v2@94.8,66.752 v2(94.8,66.8) ; v2@95.6,67.709 v2(95.6,67.793)
  Bottom Layer w0.2: v2@89.264,66.858 v2(89.264,66.886)
  other v2: 94,76.4 94.8,77.2 90.8,78 93.2,78.8 87.6,80.42

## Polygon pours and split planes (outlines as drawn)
GND on Bottom Layer "GND_L04" (solid, pour order 154): 0.225,137.075 172,137.075 172,-0.225 0.025,-0.225
5V_STLK on Bottom Layer "5V_STLK_L04" (solid, pour order 149): 42.715,94.735 42.76,94.78 72.14,94.78 72.14,59.34 72.155,59.325 42.73,59.325
1V8 on Bottom Layer "1V8_L04" (solid, pour order 0): 84.939,76.533 84.939,85.255 86.38,85.255 86.38,82.845 86.37,82.843 92.23,82.843 92.23,77.2 90.71,77.2 90.71,81.299 87.934,81.299 87.934,79.63 87.966,79.598 89.365,79.159 89.365,76.533
GND on Signal Layer 2 "GND_L03" (solid, remove dead copper, pour order 152): 0,137 172,137 172,0 0,0
VDD2_DDR on Signal Layer 2 "VDD2_DDR" (solid, remove dead copper, pour order 144): 97.557,75.295 95.405,73.143 95.405,71.413 95.543,71.275 96.075,71.275 96.075,71.26 96.33,71.006 96.33,69.119 96.572,68.877 97.557,68.877 98.8,67.634 98.8,67.25 100.575,65.475 121.35,65.475 121.35,80.473 105.891,80.534 96.44,89.985 50.853,89.985 46.246,85.378 46.246,78.14 46.918,77.468 48.216,77.468 49.219,78.471 49.219,83.775 49.539,84.095 93.76,84.095 95.32,82.536 97.557,80.298
1V8 on Signal Layer 2 "1V8" (solid, pour order 151): 60.675,96.6 60.675,93.472 105.856,93.472 105.904,85.175 117.725,85.175 117.725,96.6
VDDGPU on Signal Layer 2 "VDDGPU" (solid, remove dead copper, pour order 127): 95.348,72.122 95.348,71.47 95.61,71.208 98.541,68.277 98.541,64.841 91.09,57.39 77.655,57.39 69.27,65.607 69.27,70.917 66.599,73.523 66.599,75.759 68.13,77.29 73.63,77.29 73.63,72.863 72.549,71.782 72.549,69.54 74.374,67.715 89.374,67.715 91.607,69.923 93.267,69.923 93.441,70.097 93.441,70.49 92.994,71.003 92.994,72.331 95.14,72.331
5V_STLK on Signal Layer 2 "5V_STLK_L03" (solid, pour order 150): 43.375,82.635 68.935,82.635 68.975,82.595 68.975,66.229 43.411,66.229
3V3 on Signal Layer 2 "3V3_L03" (solid, remove dead copper, pour order 146): 58,61.394 57.939,61.394 37.983,61.394 35.711,61.394 35.711,67.822 35.711,84.011 44.436,84.011 44.436,73.55 45.447,72.539 58,72.539
VDDIO on Signal Layer 2 "VDDIO_L03" (solid, remove dead copper, pour order 145): 93.852,70.39 93.235,69.772 91.585,69.772 89.378,67.564 74.378,67.564 72.553,69.389 72.553,71.646 73.945,73.038 93.024,73.038 93.852,72.21
VDDCORE on Signal Layer 2 "VDDCORE" (solid, remove dead copper, pour order 142): 93.118,75.605 93.118,77.055 91.173,79 73.745,79 73.745,73.019 93.843,73.019 93.843,74.83
VDDCPU on Signal Layer 2 "VDDCPU" (solid, remove dead copper, pour order 143): 97.516,75.448 94.844,72.776 94.833,72.775 92.631,72.775 92.631,76.645 92.631,77.532 91.618,78.545 66.455,78.545 66.455,80.62 66.505,80.67 66.175,81 60.143,81 60.055,80.912 59.116,81.85 49.319,81.85 49.219,81.75 49.219,83.775 50.843,85.4 59.717,85.4 60.603,84.513 60.603,84.5 93.355,84.5 97.516,80.339 97.516,76.697
GND on Top Layer "GND_L01" (solid, pour order 153): 0.178,137.102 0.303,136.977 172,136.977 172,-0.323 0.103,-0.323
3V3 on Top Layer "3V3" (solid, pour order 137): 44.387,68.548 44.562,68.373 50.91,68.373 52.212,69.675 52.212,70.523 44.588,70.523 44.387,70.323
5V_STLK on Top Layer "5V_STK" (solid, pour order 111): 54.01,75.62 54.667,75.62 54.85,75.803 54.85,75.463 54.367,74.98 54.01,74.98
VDDCPU on Top Layer "I_SENS_VDDCPU_P" (solid, pour order 133): 49.312,83.845 49.312,81.998 49.835,81.475 54.25,81.475 54.245,81.48 54.245,83.845
VDDCORE on Top Layer "I_SENS_VDDCORE_P" (solid, pour order 134): 72.507,84.74 75.389,81.858 75.389,75.631 75.394,75.626 73.94,75.626 73.395,76.171 73.395,80.872 73.022,81.245 71.375,81.245 67.015,81.245 67.005,84.74
VDDGPU on Top Layer "I_SENS_VDDGPU_P" (solid, pour order 135): 73.103,75.6 73.245,75.742 73.245,78.72 68.525,78.72 68.525,75.6
VDDIO on Top Layer "VDDIO" (solid, pour order 136): 62.495,78.77 62.495,80.568 63.03,81.103 63.212,81.103 63.65,80.664 63.65,80.123 62.95,79.423 62.95,78.77
NetL6_1 on Top Layer "NetL6_1" (solid, pour order 138): 64.875,73.863 65.338,73.4 66.6,73.4 66.6,71.1 66.598,71.098 65.301,71.098 65.301,72.722 64.875,73.148
GND on Signal Layer 1 "GND_L02" (solid, remove dead copper, pour order 99): -1,138 172,138 172,-1 -1,-1

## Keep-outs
Keep-Out Layer:
  lines w0.1: 133.661,133.38 142.561,133.38 142.561,135.53 133.661,135.53 133.661,133.38

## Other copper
Top Layer:
  rectangle net VDD2_DDR: 47.155,73.8 50.125,75.6
  region net 5V_STLK: 56.73,80.524 56.631,80.425 56.275,80.425 cw(c56.275,80.775) 55.925,80.775 55.925,80.825 55.2,80.825 ccw(c55.2,80.75) 55.125,80.75 55.125,80.4 ccw(c55.327,80.397) 55.325,80.195 57.95,80.195 58.35,79.8 58.612,79.8 57.891,80.521 57.625,80.525
  region net 5V_STLK: 65.105,79.78 64.93,79.672 ccw(c65.063,79.473) 64.894,79.642 64.853,79.601 ccw(c65.113,79.342) 64.746,79.342 64.746,79.326 ccw(c65.101,79.326) 64.85,79.075 64.85,77.539 64.849,77.538 64.847,77.551 64.376,77.08 63.77,77.08 63.77,77.345 64.006,77.345 64.48,77.819 64.48,80.347 64.808,80.67 65.825,80.67 65.825,79.78
  region net GND: 56.4,79.685 56.307,79.685 ccw(c56.307,79.584) 56.235,79.655 55.955,79.375 ccw(c56.026,79.303) 55.925,79.303 55.925,78.975 56.425,78.975 cw(c56.823,78.982) 56.815,79.38 57.075,79.375 ccw(c57.075,79.423) 57.109,79.389 57.205,79.485
  region net GND: 63.725,76 63.65,75.925 63.572,75.925 cw(c63.572,75.798) 63.662,75.888 63.688,75.862 ccw(c63.778,75.952) 63.778,75.825 64.447,75.825 cw(c64.447,75.698) 64.537,75.788 64.6,75.725 64.729,75.854 cw(c64.78,75.803) 64.78,75.875
  region net NetL1_1: 59.072,81.875 ccw(c58.769,81.883) 58.978,82.102 58.955,82.125 58.955,82.187 59.026,82.194 ccw(c59.025,82.194) 59.025,82.195 59.175,82.075
  region net 5V_STLK: 65.695,78.175 65.695,77.32 65.625,77.25 65.5,77.375 64.9,77.375 65.055,77.53 65.055,78.175
  region net 5V_STLK: 65.625,77.25 65.05,76.675 64.375,76.675 64.375,76.85 64.9,77.375
  region net 5V_STLK: 54.375,72.9 54.216,72.9 54.189,72.874 54.148,72.842 54.102,72.815 54.054,72.795 54.003,72.782 53.951,72.775 53.925,72.774 53.425,72.774 53.399,72.775 53.347,72.782 53.296,72.795 53.248,72.815 53.202,72.842 53.161,72.874 53.15,72.45 53.15,71.945 52.875,71.945 52.875,71.305 53.33,71.305 54.099,72.074 54.099,72.184 54.103,72.227 54.113,72.27 54.129,72.31 54.152,72.346 54.18,72.379 54.538,72.737
  region net 5V_STLK: 51.575,71.948 52.225,71.948 52.225,71.305 51.92,71.305 51.825,71.4 51.575,71.4
  region net 5V_STLK: 54.75,75.62 54.75,75.4 54.33,74.98 52.65,74.98 52.65,75.525 52.9,75.525 52.995,75.62
  region net 5V_STLK: 65.575,73.875 65.575,74.125 64.675,75.025 65.425,75.025 65.747,74.703
  region net 5V_STLK: 65.575,73.85 65.477,73.948 65.477,74.625 66.12,74.625 66.12,73.895 66.075,73.85 66.075,73.6 65.575,73.6
  region net 5V_STLK: 58.675,81.85 58.77,81.755 58.77,81.45 58.13,81.45 58.13,81.805 58.175,81.85 58.175,82.1 58.675,82.1
  region net 5V_STLK: 58.925,79.725 58.9,79.725 58.13,80.495 58.13,80.825 58.77,80.825 58.77,80.605 58.9,80.475 58.9,79.925
  region net 5V_STLK: 65.675,81 65.825,80.85 65.825,80.6 65.025,80.6 65.025,80.85 65.175,81 65.175,81.25 65.675,81.25
  region net 5V_STLK: 65.625,79.35 65.775,79.2 65.775,78.95 64.975,78.95 64.975,79.2 65.125,79.35 65.125,79.6 65.625,79.6
  region net 5V_STLK: 54.75,81.3 54.795,81.345 55.15,81.345 55.15,80.65 54.9,80.65 54.75,80.8 54.5,80.8 54.5,81.3
  region net GND: 51.575,72.75 51.62,72.705 52.18,72.705 52.225,72.75 52.225,73.345 51.92,73.345 51.825,73.25 51.575,73.25
  region net GND: 50.525,72.798 50.675,72.648 50.675,72.398 49.8,72.398 49.8,72.823 50.025,73.048 50.525,73.048
  region net GND: 50.525,72.798 50.375,72.648 50.375,72.398 51.2,72.398 51.2,72.873 51.025,73.048 50.525,73.048
  region net GND: 72.3,73.298 72.3,74.651 70.9,74.651 70.9,73.298
  region net GND: 59.525,87.425 59.675,87.275 59.675,87.025 58.8,87.025 58.8,87.45 59.025,87.675 59.525,87.675
  region net GND: 59.525,87.425 59.375,87.275 59.375,87.025 60.2,87.025 60.2,87.5 60.025,87.675 59.525,87.675
  region net GND: 57.675,87.425 57.825,87.275 57.825,87.025 56.95,87.025 56.95,87.45 57.175,87.675 57.675,87.675
  region net GND: 57.675,87.425 57.525,87.275 57.525,87.025 58.35,87.025 58.35,87.5 58.175,87.675 57.675,87.675
  region net GND: 56.1,81.323 56.297,81.52 56.75,81.52 56.75,80.63 56.293,80.63 56.1,80.823
  region net GND: 45.125,72.798 44.975,72.648 44.975,72.398 45.8,72.398 45.8,72.873 45.625,73.048 45.125,73.048
  region net GND: 45.125,72.798 45.275,72.648 45.275,72.398 44.4,72.398 44.4,72.823 44.625,73.048 45.125,73.048
  region net GND: 46.925,72.798 46.775,72.648 46.775,72.398 47.6,72.398 47.6,72.873 47.425,73.048 46.925,73.048
  region net GND: 46.925,72.798 47.075,72.648 47.075,72.398 46.2,72.398 46.2,72.823 46.425,73.048 46.925,73.048
  region net GND: 45.1,74.7 45.295,74.895 46.075,74.895 46.075,74.005 45.295,74.005 45.1,74.2
  region net GND: 48.725,72.798 48.575,72.648 48.575,72.398 49.4,72.398 49.4,72.873 49.225,73.048 48.725,73.048
  region net GND: 48.725,72.798 48.875,72.648 48.875,72.398 48,72.398 48,72.823 48.225,73.048 48.725,73.048
  region net GND: 57.075,79.375 56.74,79.375 56.74,79.385
  region net GND: 63.421,78.656 63.52,78.656 63.549,78.653 63.578,78.644 63.604,78.63 63.627,78.612 63.645,78.589 63.67,78.555 63.67,78.23 63.77,78.23 63.77,78.93 63.421,78.93
  region net GND: 53.425,72.952 53.23,73.147 53.23,73.602 54.12,73.602 54.12,73.147 53.925,72.952
  region net GND: 64.33,76.125 64.78,76.125 64.78,75.825 64.655,75.7 64.48,75.875 64.33,75.875
  region net GND: 45.1,77.3 45.295,77.495 46.075,77.495 46.075,76.605 45.295,76.605 45.1,76.8
  region net GND: 45.1,76 45.295,76.195 46.075,76.195 46.075,75.305 45.295,75.305 45.1,75.5
  region net GND: 51.45,85.873 51.645,85.678 51.645,85.223 50.755,85.223 50.755,85.678 50.95,85.873
  region net GND: 52.75,85.873 52.945,85.678 52.945,85.223 52.055,85.223 52.055,85.678 52.25,85.873
  region net GND: 54.05,85.873 54.245,85.678 54.245,85.223 53.355,85.223 53.355,85.678 53.55,85.873
  region net GND: 55.775,83.373 55.97,83.178 55.97,82.723 55.08,82.723 55.08,83.178 55.275,83.373
  region net GND: 55.825,87.425 55.675,87.275 55.675,87.025 56.5,87.025 56.5,87.5 56.325,87.675 55.825,87.675
  region net GND: 55.825,87.425 55.975,87.275 55.975,87.025 55.1,87.025 55.1,87.45 55.325,87.675 55.825,87.675
  region net GND: 70.45,80.825 70.645,80.63 70.645,79.775 69.755,79.775 69.755,80.63 69.95,80.825
  region net GND: 69.15,80.825 69.345,80.63 69.345,79.775 68.455,79.775 68.455,80.63 68.65,80.825
  region net GND: 67.7,86.825 67.895,86.63 67.895,85.775 67.005,85.775 67.005,86.63 67.2,86.825
  region net GND: 74.1,73.298 74.1,74.651 72.7,74.651 72.7,73.298
  region net GND: 70.5,73.298 70.5,74.651 69.1,74.651 69.1,73.298
  region net GND: 73.05,80.825 73.245,80.63 73.245,79.775 72.355,79.775 72.355,80.63 72.55,80.825
  region net GND: 71.75,80.825 71.945,80.63 71.945,79.775 71.055,79.775 71.055,80.63 71.25,80.825
  region net GND: 68.975,86.825 69.17,86.63 69.17,85.775 68.28,85.775 68.28,86.63 68.475,86.825
  region net GND: 70.25,86.825 70.445,86.63 70.445,85.775 69.555,85.775 69.555,86.63 69.75,86.825
  region net GND: 71.525,86.825 71.72,86.63 71.72,85.775 70.83,85.775 70.83,86.63 71.025,86.825
  region net GND: 67.8,78.325 67.605,78.13 66.75,78.13 66.75,79.02 67.605,79.02 67.8,78.825
  region net GND: 67.825,79.975 67.63,79.78 66.775,79.78 66.775,80.67 67.63,80.67 67.825,80.475
  region net GND: 68.002,74.375 67.807,74.18 67.5,74.18 67.5,75.07 67.975,75.07 68.17,74.875 68.17,74.375
  region net VDD2_DDR: 47.795,77.615 47.795,77.731 48.148,78.084 48.148,79.215 47.795,79.215 47.155,79.215 46.798,79.215 46.798,78.019 47.155,77.662 47.155,77.238 47.795,77.238
  region net VDDIO: 73.08,70.835 73.08,70.719 72.727,70.366 72.727,69.235 73.08,69.235 73.72,69.235 74.077,69.235 74.077,70.431 73.72,70.788 73.72,71.212 73.08,71.212
  pour cut-out: 74.825,62.125 78.033,62.125 78.26,62.125 78.785,61.6 78.785,59.714 78.283,59.211 74.825,59.211
  pour cut-out: 68.455,77.45 67.395,77.45 67.395,75.35 68.455,75.35
  pour cut-out: 74.1,71.925 69.13,71.925 69.13,72.575 74.1,72.575
  pour cut-out: 67.4,73.075 66.6,73.075 66.6,70.975 67.4,70.975
  pour cut-out: 67.355,72.875 69.13,72.875 69.13,71.6 67.8,71.6
  pour cut-out: 52.3,81.605 52.3,80.545 54.4,80.545 54.4,81.605
  pour cut-out: 66.945,83.25 65.885,83.25 65.885,81.15 66.945,81.15
  region net NetL1_1: 59.495,82.275 59.15,81.93 58.695,82.385 58.695,84.075 59.495,84.075
  pour cut-out: 58.655,84.225 57.935,84.225 57.935,82.125 58.655,82.125
  region net NetL2_1: 65.15,82.225 65.15,81.45 65.015,81.45 64.325,80.76 64.325,78 63.85,77.525 63.525,77.525 63.525,77.675 63.614,77.675 63.77,77.831 63.95,78.011 64.005,78.094 64.025,78.191 64.025,78.742 64.07,78.85 64.07,79.01 64.009,79.157 63.897,79.269 63.77,79.322 63.75,79.325 63.75,83.102 64.098,83.45 65.015,83.45 65.15,83.315 65.15,83.2
  region net NetL5_1: 50.925,75.948 51.15,76.173 52.525,76.173 52.525,74.323 52.002,73.8 51.725,73.8 50.925,73.8
  pour cut-out: 49.995,73.65 51.055,73.65 51.055,75.75 49.995,75.75
  region net NetL4_1: 66.025,77.6 66.025,75.6 66.934,75.6 66.934,77.6
  region net NetL7_1: 54.375,70.35 54.075,70.05 53.3,70.05 53.3,70.95 54.375,72.02
  region net NetL3_1: 54.075,78.975 52.888,80.162 53.988,80.162 54.075,80.075 57.68,80.075 57.92,79.835 56.29,79.835 56.267,79.833 56.248,79.829 56.22,79.82 56.201,79.813 56.175,79.799 56.158,79.788 56.135,79.769 55.841,79.474 55.822,79.452 55.811,79.435 55.802,79.419 55.79,79.39 55.786,79.378 55.781,79.362 55.777,79.342 55.776,79.327 55.774,79.313 55.774,78.975
  region net NetL3_1: 55.283,80.045 55.254,80.048 55.225,80.057 55.151,80.089 55.125,80.103 55.103,80.122 55.047,80.18 55.028,80.203 55.014,80.229 54.988,80.294 54.981,80.316 54.958,80.347 54.933,80.367 54.897,80.391 54.851,80.4 54.075,80.4 54.075,79.263
  pour cut-out: 53,72.6 51.05,72.6 51.05,72.025 53,72.025
  pour cut-out: 44.4,70.773 51.05,70.773 51.05,71.573 44.4,71.573
  pour cut-out: 53.44,71.1 52.38,71.1 52.38,69 53.44,69
  pour cut-out: 75.75,68.05 75.75,65.25 78.28,65.25 78.28,68.05
  pour cut-out: 103.034,80.609 107.275,84.85 118.675,84.85 123.745,79.78 123.745,67.457 117.663,61.374 106.253,61.374 105.118,62.509 86.244,62.509 86.244,80.609
  text "1" at 134.025,133.811 h2
Signal Layer 1:
  text "2" at 135.309,133.811 h2
Signal Layer 2:
  text "5" at 140.661,133.833 h2
Bottom Layer:
  pour cut-out: 122.6,78.19 122.6,67.775 100.225,67.775 97.738,70.262 97.738,75.589 100.338,78.19
  text "6" at 142.16,133.822 h2

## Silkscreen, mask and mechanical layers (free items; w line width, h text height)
Top Overlay:
  text "J" at 36.706,115.692 h15
  text "VBAT" at 63.012,59.791 h1.2
Top Solder:
  region: 133.736,135.455 133.736,133.455 142.486,133.455 142.486,135.455
Bottom Solder:
  region: 133.736,135.455 133.736,133.455 142.486,133.455 142.486,135.455
M1-Board Shape:
  lines w0.1: 1,137 ccw(c1,136) 0,136 0,95 0,1 ccw(c1,1) 1,0 171,0 ccw(c171,1) 172,1 172,136 ccw(c171,136) 171,137 ; 1,137 1,137 ; 1,137 171,137 ; 171,137 171,137
M2-Board Dimensions:
  lines w0.1: 1,137 ccw(c1,136) 0,136 0,1 ccw(c1,1) 1,0 171,0 ccw(c171,1) 172,1 172,136 ccw(c171,136) 171,137 ; 1,137 1,137 ; 1,137 171,137 ; 171,137 171,137
Drill Drawing:
  drawing of 183 lines, arcs and shapes, not listed
  text "PCB SPECIFICATIONS :" at 3.455,183.85 h3
  text "MINIMUN PARAMETERS" at 155.325,183.145 h3
  text "PCB : TYPE 3" at 194.663,183.121 h3
  text "A.   MATERIAL :" at 3.455,179.85 h3
  text "FR-4" at 41.955,179.85 h3
  text "TG-170" at 58.455,179.85 h3
  text "X  TG-150" at 76.705,179.85 h3
  text "TG-140" at 92.705,179.85 h3
  text "DEFAULT" at 155.325,177.645 h3
  text "ASPECT-RATIO, AXE Z :" at 194.663,177.621 h3
  text "B.   MATERIAL FAMILY :" at 3.455,176.85 h3
  text "N/A" at 41.955,176.85 h3
  text "C.   SOLDERMASK COLOR :" at 3.455,173.85 h3
  text "GREEN" at 41.955,173.85 h3
  text "X  BLUE" at 58.455,173.85 h3
  text "RED" at 76.705,173.85 h3
  text "BLACK" at 92.705,173.85 h3
  text "TRACKS : 0.100mm           / GAPS : 0.100mm" at 155.325,171.895 h3
  text "6 :1  to  8 :1 / LEVEL \"B\"" at 194.682,170.874 h3
  text "D.   SILKSCREEN COLOR :" at 3.455,170.85 h3
  text "X  WHITE" at 41.955,170.85 h3
  text "YELLOW" at 58.455,170.85 h3
  text "BLACK" at 76.705,170.85 h3
  text "E.   SURFACE FINISH :" at 3.455,167.85 h3
  text "X  ENIG" at 41.955,167.85 h3
  text "IMMERSION SILVER" at 58.455,167.85 h3
  text "IMMERSION TIN" at 92.705,167.85 h3
  text "BGA :" at 155.3,167.07 h3
  text "Layer" at 244.479,166.45 h2
  text "Name" at 252.853,166.45 h2
  text "Material" at 269.05,166.45 h2
  text "Thickness" at 283.604,166.45 h2
  text "Constant" at 295.559,166.45 h2
  text "HASL" at 41.955,164.85 h3
  text "HASL (PB-FREE)" at 58.455,164.85 h3
  text "GOLDEN FINGER" at 92.705,164.85 h3
  text "Top Overlay" at 252.853,162.45 h2
  text "F.   IMPEDANCE CONTROL :" at 3.455,161.85 h3
  text "NO" at 41.955,161.85 h3
  text "X  YES" at 58.455,161.85 h3
  text "TRACKS : 0.090mm           / GAPS : 0.090mm" at 155.3,161.32 h3
  text "G.   THROUGH VIA :" at 3.455,158.85 h3
  text "PLUG THE VIAS WHICH ARE COVERED WITH SOLDERMASK ONE OR TWO SIDE." at 41.955,158.85 h3
  text "Top Solder" at 252.853,158.45 h2
  text "Solder Resist" at 269.05,158.45 h2
  text "0.025mm" at 283.604,158.45 h2
  text "3.5" at 295.559,158.45 h2
  text "PLUG MATERIAL :" at 41.955,155.85 h3
  text "X  SOLDERMASK" at 67.455,155.85 h3
  text "NON-CONDUCTIVE EPOXY." at 92.705,155.85 h3
  text "1" at 244.479,154.45 h2
  text "Top Layer" at 252.853,154.45 h2
  text "0.037mm" at 283.604,154.45 h2
  text "H.   STACK-UP :" at 3.455,152.85 h3
  text "SEE LAYER STACK-UP SEQUENCE FOR OVERALL THICKNESS." at 41.955,152.85 h3
  text "Dielectric 1" at 252.853,150.45 h2
  text "0.070mm" at 283.604,150.45 h2
  text "3.8" at 295.559,150.45 h2
  text "2" at 244.478,146.45 h2
  text "Signal Layer 1" at 252.853,146.45 h2
  text "0.035mm" at 283.604,146.45 h2
  text "Dielectric 2" at 252.853,142.45 h2
  text "1.330mm" at 283.604,142.45 h2
  text "4.3" at 295.559,142.45 h2
  text "3" at 244.479,138.45 h2
  text "Signal Layer 2" at 252.853,138.45 h2
  text "0.035mm" at 283.604,138.45 h2
  text "Dielectric 3" at 252.853,134.45 h2
  text "0.070mm" at 283.604,134.45 h2
  text "3.8" at 295.559,134.45 h2
  text "4" at 244.479,130.45 h2
  text "Bottom Layer" at 252.853,130.45 h2
  text "0.037mm" at 283.604,130.45 h2
  text "Bottom Solder" at 252.853,126.45 h2
  text "Solder Resist" at 269.05,126.45 h2
  text "0.025mm" at 283.604,126.45 h2
  text "3.5" at 295.559,126.45 h2
  text "Bottom Overlay" at 252.853,122.45 h2
  text "Symbol" at 183.644,20.309 h2.4
  text "Count" at 193.043,20.309 h2.4
  text "Hole Size" at 202.8,20.309 h2.4
  text "Plated" at 221.077,20.309 h2.4
  text "Hole Type" at 229.328,20.309 h2.4
  text "Drill Layer Pair" at 241.34,20.309 h2.4
  text "Via/Pad" at 264.12,20.309 h2.4
  text "Pad Shape" at 273.963,20.309 h2.4
  text "Hole Length" at 286.82,20.309 h2.4
  text "448" at 193.043,16.166 h2
  text "0.200mm (7.87mil)" at 202.8,16.166 h2
  text "PTH" at 221.077,16.166 h2
  text "Round" at 229.328,16.166 h2
  text "Top Layer - Bottom Layer" at 241.34,16.166 h2
  text "Via" at 264.12,16.166 h2
  text "Rounded" at 273.963,16.166 h2
  text "-" at 286.82,16.166 h2
  text "D" at 182.856,15.912 h1.84
  text "3" at 193.043,12.023 h2
  text "0.250mm (9.84mil)" at 202.8,12.023 h2
  text "PTH" at 221.077,12.023 h2
  text "Round" at 229.328,12.023 h2
  text "Top Layer - Bottom Layer" at 241.34,12.023 h2
  text "Via" at 264.12,12.023 h2
  text "Rounded" at 273.963,12.023 h2
  text "-" at 286.82,12.023 h2
  text "E" at 182.856,11.769 h1.84
  text "387" at 193.043,7.88 h2
  text "0.350mm (13.78mil)" at 202.8,7.88 h2
  text "PTH" at 221.077,7.88 h2
  text "Round" at 229.328,7.88 h2
  text "Top Layer - Bottom Layer" at 241.34,7.88 h2
  text "Via" at 264.12,7.88 h2
  text "Rounded" at 273.963,7.88 h2
  text "-" at 286.82,7.88 h2
  text "F" at 182.856,7.626 h1.84
  text "2" at 193.043,3.737 h2
  text "0.500mm (19.69mil)" at 202.8,3.737 h2
  text "PTH" at 221.077,3.737 h2
  text "Round" at 229.328,3.737 h2
  text "Top Layer - Bottom Layer" at 241.34,3.737 h2
  text "Pad" at 264.12,3.737 h2
  text "Rounded" at 273.963,3.737 h2
  text "-" at 286.82,3.737 h2
  text "840 Total" at 193.043,-0.407 h2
